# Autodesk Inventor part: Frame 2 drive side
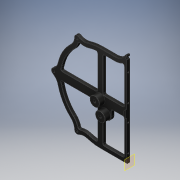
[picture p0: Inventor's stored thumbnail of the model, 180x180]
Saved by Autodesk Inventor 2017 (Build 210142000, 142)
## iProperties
Created: 2016-06
Part Number: Frame 2 drive side
Material: Generic
Document SubType Name: Modeling
Designer: Stan
Density: 1 g/cm^3
Appearance: Glossy - Black
Author: Stan
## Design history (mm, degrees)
sketch "Sketch1"
  geometry: L1 (9.525, 88.9)-(33.07, 88.9); L2 (0, -98.425)-(60.555, -98.425); L3 (9.525, -88.9)-(51.041, -88.9); L4 (6.35, 85.725)-(6.35, 12.7); L5 (6.35, -37.963)-(6.35, -85.725); L6 (-6.35, 85.194)-(-6.35, 12.7); L7 (-6.35, -12.7)-(-6.35, -85.194); L8 (-85.613, -9.525)-(-9.525, -9.525); L9 (28.461, -9.525)-(51.041, -9.525); L10 (-85.613, 9.525)-(-9.525, 9.525); L11 (9.525, 9.525)-(51.041, 9.525); L12 (33.07, 98.425)-(0, 98.425); L13 (54.216, 90.23)-(54.216, 12.7); L14 (54.216, -12.7)-(54.216, -85.725); L15 (60.555, 114.281)-(60.555, 110.471); L16 (60.555, 105.391)-(60.555, -98.425); L17 (12.586, -36.513)-(9.525, -36.512); L18 (25.286, -23.812)-(25.286, -12.7); C1 r 3.175 at (0, 0); C2 r 2.54 at (-104.775, 0); C3 r 2.54 at (-52.387, -90.738); C4 r 2.54 at (-52.388, 90.738); C5 r 3.175 at (12.586, -23.812); A1 r 3.175 centre (9.525, -85.725) between (6.35, -85.725) and (9.525, -88.9); A2 r 3.175 centre (9.525, 85.725) between (9.525, 88.9) and (6.35, 85.725); A3 r 3.175 centre (-9.525, -12.7) between (-6.35, -12.7) and (-9.525, -9.525); A4 r 3.175 centre (51.041, -12.7) between (54.216, -12.7) and (51.041, -9.525); A5 r 3.175 centre (-9.525, 12.7) between (-9.525, 9.525) and (-6.35, 12.7); A6 r 3.175 centre (9.525, 12.7) between (6.35, 12.7) and (9.525, 9.525); A7 r 3.175 centre (51.041, 12.7) between (51.041, 9.525) and (54.216, 12.7); A8 r 98.425 centre (0, 0) between (0, 98.425) and (-29.099, 94.025); A9 r 98.425 centre (0, 0) between (-66.878, 72.213) and (-95.978, 21.812); A10 r 98.425 centre (0, 0) between (-95.978, -21.812) and (-66.878, -72.213); A11 r 98.425 centre (0, 0) between (-29.099, -94.025) and (0, -98.425); A12 r 88.9 centre (0, 0) between (-9.878, 88.35) and (-26.283, 84.926); A13 r 3.175 centre (-9.525, 85.194) between (-6.35, 85.194) and (-9.878, 88.35); A14 r 88.9 centre (0, 0) between (-60.406, 65.225) and (-86.69, 19.701); A15 r 88.9 centre (0, 0) between (-86.69, -19.701) and (-60.406, -65.225); A16 r 88.9 centre (0, 0) between (-26.283, -84.926) and (-9.878, -88.35); A17 r 3.175 centre (-9.525, -85.194) between (-9.878, -88.35) and (-6.35, -85.194); A18 r 6.35 centre (-104.775, 0) between (-107.969, 5.488) and (-107.969, -5.488); A19 r 25.4 centre (-120.746, 27.441) between (-107.969, 5.488) and (-95.978, 21.812); A20 r 34.925 centre (-120.746, 27.441) between (-88.541, 13.928) and (-86.69, 19.701); A21 r 3.175 centre (-85.613, 12.7) between (-88.541, 13.928) and (-85.613, 9.525); A22 r 25.4 centre (-120.746, -27.441) between (-95.978, -21.812) and (-107.969, -5.488); A23 r 34.925 centre (-120.746, -27.441) between (-86.69, -19.701) and (-88.541, -13.928); A24 r 3.175 centre (-85.613, -12.7) between (-85.613, -9.525) and (-88.541, -13.928); A25 r 6.35 centre (-52.387, -90.738) between (-58.737, -90.76) and (-49.232, -96.248); A26 r 25.4 centre (-84.137, -90.849) between (-58.737, -90.76) and (-66.878, -72.213); A27 r 34.925 centre (-84.137, -90.849) between (-50.239, -82.443) and (-60.406, -65.225); A28 r 3.175 centre (-47.157, -81.679) between (-50.239, -82.443) and (-46.278, -84.73); A29 r 25.4 centre (-36.609, -118.29) between (-29.099, -94.025) and (-49.232, -96.248); A30 r 34.925 centre (-36.609, -118.29) between (-26.283, -84.926) and (-46.278, -84.73); A31 r 6.35 centre (-52.388, 90.738) between (-49.232, 96.248) and (-58.737, 90.76); A32 r 25.4 centre (-36.609, 118.29) between (-49.232, 96.248) and (-29.099, 94.025); A33 r 34.925 centre (-36.609, 118.29) between (-46.278, 84.73) and (-26.283, 84.926); A34 r 3.175 centre (-47.157, 81.679) between (-46.278, 84.73) and (-50.239, 82.443); A35 r 25.4 centre (-84.137, 90.849) between (-66.878, 72.213) and (-58.737, 90.76); A36 r 34.925 centre (-84.137, 90.849) between (-60.406, 65.225) and (-50.239, 82.443); A37 r 25.4 centre (33.07, 123.825) between (33.07, 98.425) and (55.067, 111.125); A38 r 34.925 centre (33.07, 123.825) between (33.07, 88.9) and (49.544, 93.029); A39 r 3.175 centre (51.041, 90.23) between (54.216, 90.23) and (49.544, 93.029); A40 r 3.175 centre (51.041, -85.725) between (51.041, -88.9) and (54.216, -85.725); A41 r 6.35 centre (60.555, 107.931) between (60.555, 114.281) and (55.067, 111.125); A42 r 2.54 centre (60.555, 107.931) between (60.555, 110.471) and (60.555, 105.391); A43 r 3.175 centre (9.04, -39.65) between (9.525, -36.512) and (6.35, -37.963); A44 r 12.7 centre (12.586, -23.812) between (12.586, -36.513) and (25.286, -23.812); A45 r 3.175 centre (28.461, -12.7) between (28.461, -9.525) and (25.286, -12.7); 3 further points
  constraints: 90 point on circle, 50 centre point, 36 end point, 2 point on line, 2 tangent
  dimensions: "d24" = 23.8125 vertical distance of C5.centre point (0, 0); "d25" = 9.525 distance between parallel lines of L2 L3; "d26" = 12.7 radius of A44; "d27" = 6.35 diameter of C5; "d28" = 6.35 diameter of C1; "d29" = 9.525 distance from line of L9 point (0, 0); "d30" = 3.175 radius of A45 (derived)
workplane "Work Plane1"
sketch "Sketch2"
  geometry: C1 r 1.587 at (-3.175, 177.8); C2 r 1.587 at (-3.175, 117.475); C3 r 1.587 at (-3.175, 79.375); C4 r 1.587 at (-3.175, 19.05); 1 further point
  constraints: 4 centre point
  dimensions: "d3" = 60.325 distance of C3.centre C4.centre; "d4" = 60.325 distance of C1.centre C2.centre; "d13" = 3.175 diameter of C1; "d14" = 3.175 diameter of C2; "d15" = 3.175 diameter of C3; "d16" = 3.175 diameter of C4; "d36" = 38.1 distance of C3.centre C2.centre
extrude "Extrusion3" join sketch "Sketch1" distance "d19" = 6.35; taper "d20" = 0 deg
fillet "Fillet2" dims "d23" = 0.79375
sketch "Sketch3"
  geometry: C1 r 3.175 at (12.586, -23.812) reference; C2 r 11.113 at (12.586, -23.812); C3 r 3.179 at (12.586, -23.812); C4 r 11.113 at (0, 0); C5 r 3.175 at (0, 0); 1 further point
  constraints: 4 centre point, 4 coincident
  dimensions: "d31" = 22.225 diameter of C2; "d32" = 22.225 diameter of C4
extrude "Extrusion5" join sketch "Sketch3" distance "d33" = 12.7; taper "d34" = 0 deg
fillet "Fillet3" dims "d35" = 0.79375
extrude "Extrusion6" cut sketch "Sketch2" distance "d37" = 6.35; taper "d38" = 0 deg
sketch "Sketch4"
  geometry: L1 (60.555, 8.752)-(60.555, -8.764); A1 r 9.816 centre (64.987, -0.006) between (60.555, 8.752) and (60.555, -8.764); 2 further points
  constraints: 2 end point, 2 point on circle, 1 centre point, 1 vertical
extrude "Extrusion7" join sketch "Sketch4" distance "d39" = 3.175; taper "d40" = 0 deg
body "Solid1"
